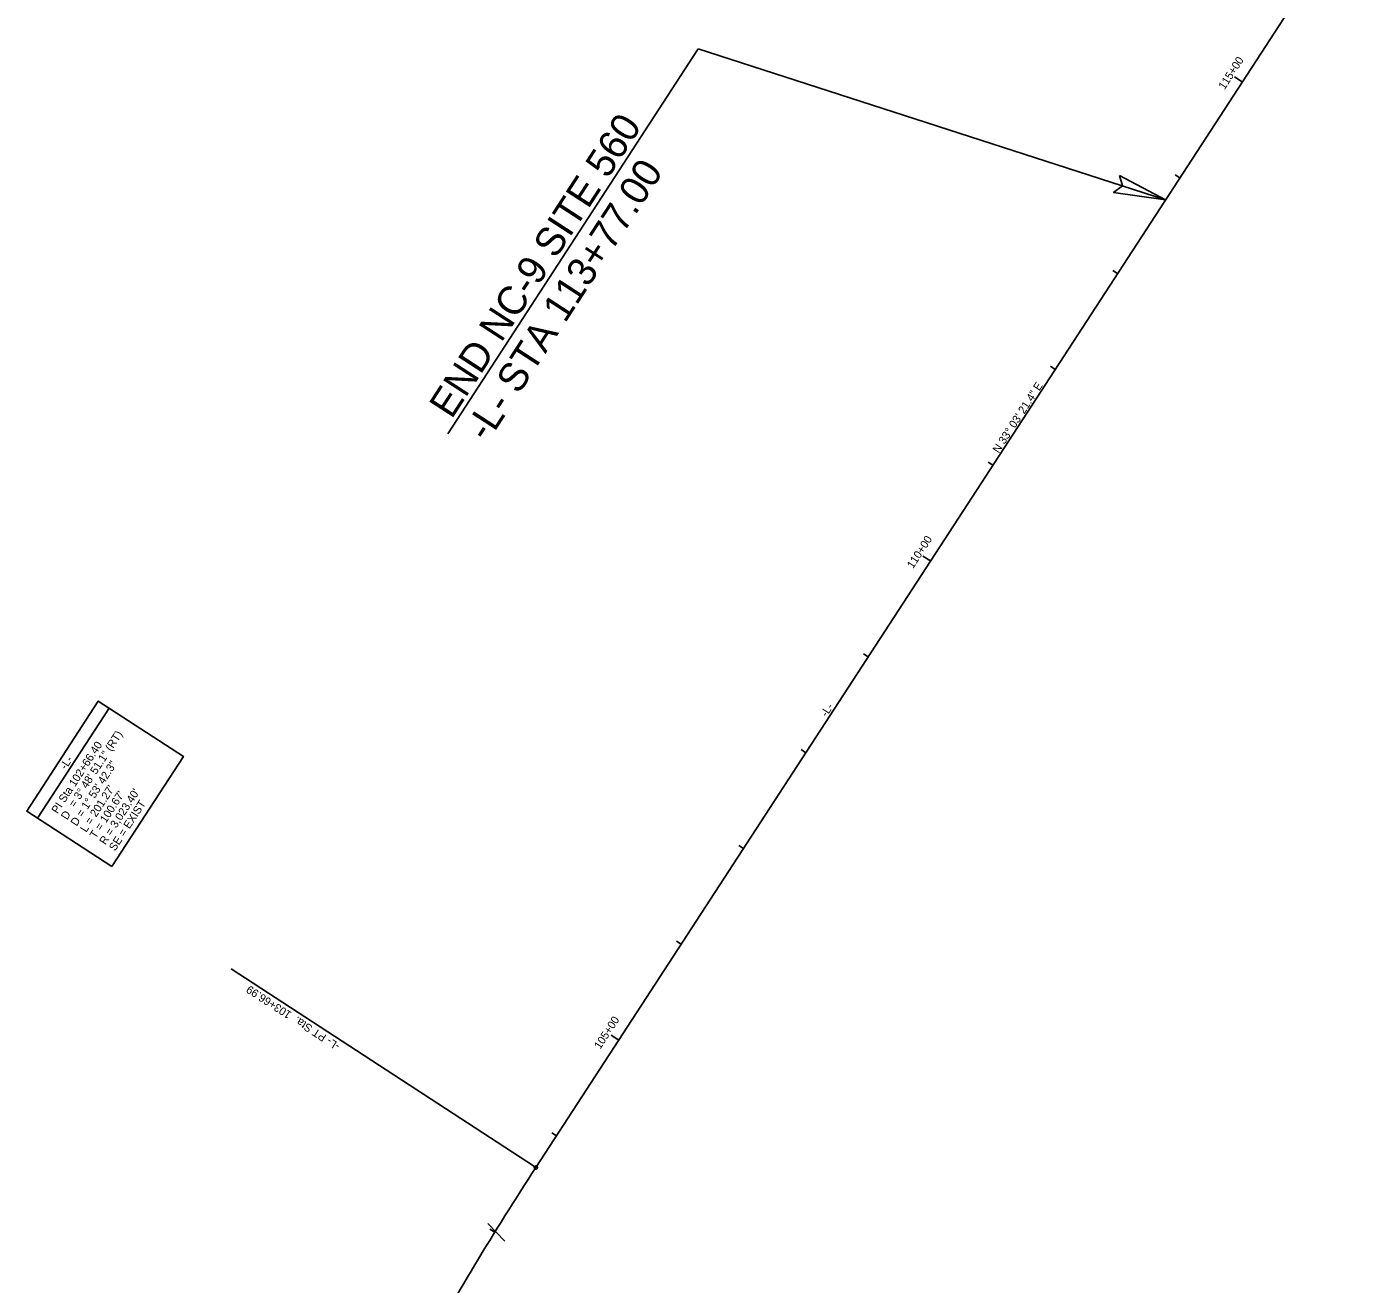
# Model space of a CAD drawing. Extents: x 1019959 to 1023888, y 635993 to 644996.
# Drawn here: x 1022370 to 1023541, y 643068 to 644168 of the extents above; entities that cross this region are included whole.
import ezdxf

# ---------------------------------------------------------------- set-up
doc = ezdxf.new("R2010")
doc.units = 0
for name, color, linetype in [('Cogo Default Point CELL', 7, 'Continuous'), ('COGO Default Point Elevation', 7, 'Continuous'), ('COGO Default Point Number', 7, 'Continuous'), ('Exist Other Culture Well CELL', 7, 'Continuous'), ('Exist Roads EOT', 7, 'Continuous'), ('Exist Structure Minor Pipes CMP 18 Inch Cogo Comment', 7, 'Continuous'), ('Exist Structure Minor Pipes CMP 18 Inch Cogo Number', 7, 'Continuous'), ('Exist Structure Minor Pipes CMP 24 Inch Cogo Number', 7, 'Continuous'), ('Exist Utilities Power Pole CELL', 7, 'Continuous'), ('Exist Utilities Power Pole Cogo Elevation', 7, 'Continuous'), ('Exist Utilities Power Pole Cogo Number', 7, 'Continuous')]:
    doc.layers.add(name, color=color, linetype=linetype)

msp = doc.modelspace()

# ---------------------------------------------------------------- linework, layer by layer
at = {"layer": 'COGO Default Point Elevation'}
for p, q in [((1023379.3, 644035.7), (1023375.1, 644038.4)), ((1023324.7, 643951.9), (1023320.5, 643954.6)), ((1023270.2, 643868.1), (1023266, 643870.8)), ((1023215.6, 643784.3), (1023211.4, 643787)), ((1023106.5, 643616.6), (1023102.3, 643619.4)), ((1023052, 643532.8), (1023047.8, 643535.6)), ((1022997.4, 643449), (1022993.2, 643451.7)), ((1022942.9, 643365.2), (1022938.7, 643367.9)), ((1022833.8, 643197.6), (1022829.6, 643200.3)), ((1022779.9, 643113.4), (1022775.6, 643116))]:
    msp.add_line(p, q, dxfattribs=at)
at = {"layer": 'COGO Default Point Number'}
for p, q in [((1023433.8, 644119.5), (1023427.1, 644123.9)), ((1023161.1, 643700.5), (1023154.4, 643704.8)), ((1022888.3, 643281.4), (1022881.6, 643285.8))]:
    msp.add_line(p, q, dxfattribs=at)
at = {"layer": 'Exist Other Culture Well CELL'}
for p in [(1022738.8, 643811.7), (1023366.7, 644016.4)]:
    msp.add_line(p, (1022957.7, 644148.5), dxfattribs=at)
at = {"layer": 'Exist Roads EOT'}
msp.add_line((1022814.5, 643170.7), (1022549, 643343.6), dxfattribs=at)
msp.add_circle((1022815.8, 643169.9), 1.5, dxfattribs=at)
at = {"layer": 'Exist Structure Minor Pipes CMP 18 Inch Cogo Comment'}
msp.add_lwpolyline([(1023326.3, 644037.6), (1023366.7, 644016.4), (1023321.2, 644022.7), (1023329.1, 644028.6)], close=True, dxfattribs=at)
at = {"layer": 'Exist Structure Minor Pipes CMP 18 Inch Cogo Number'}
msp.add_line((1022815.8, 643169.9), (1023540.5, 644283.5), dxfattribs=at)
msp.add_arc((1025349.8, 641520.8), 3023.4, 146.9441, 150.7582, dxfattribs=at)
at = {"layer": 'Exist Structure Minor Pipes CMP 24 Inch Cogo Number'}
msp.add_line((1022773.7, 643120.9), (1022788.7, 643105.6), dxfattribs=at)
at = {"layer": 'Exist Utilities Power Pole CELL'}
msp.add_line((1022815.8, 643169.9), (1023540.5, 644283.5), dxfattribs=at)
msp.add_arc((1025349.8, 641520.8), 3023.4, 146.9441, 150.7582, dxfattribs=at)
at = {"layer": 'Exist Utilities Power Pole Cogo Elevation'}
msp.add_line((1022379.8, 643475.4), (1022442.4, 643571.7), dxfattribs=at)
msp.add_lwpolyline([(1022444.8, 643433.2), (1022507.4, 643529.5), (1022432.9, 643577.9), (1022370.3, 643481.6)], close=True, dxfattribs=at)

# ---------------------------------------------------------------- texts
at = {"layer": 'Cogo Default Point CELL'}
for s, p in [('115+00', (1023418.3, 644112.3)), ('110+00', (1023145.7, 643693.3)), ('105+00', (1022872, 643272.9))]:
    msp.add_text(s, height=7, rotation=56.9441, dxfattribs=at).set_placement(p)
at = {"layer": 'Exist Other Culture Well CELL'}
for s, p in [('END NC-9 SITE 560', (1022742, 643823.9)), ('-L- STA 113+77.00', (1022773.4, 643803.5))]:
    msp.add_text(s, height=25, rotation=56.9918, dxfattribs=at).set_placement(p)
at = {"layer": 'Exist Roads EOT'}
msp.add_text('-L- PT Sta.  103+66.99', height=7, rotation=146.9441, dxfattribs=at).set_placement((1022644.9, 643277.8))
at = {"layer": 'Exist Utilities Power Pole Cogo Elevation'}
for s, p in [('= 3%%d 48\' 51.1" (RT)', (1022412.3, 643484.4)), ('PI Sta 102+66.40', (1022397.2, 643478.9)), ('-L-', (1022404.6, 643517.5)), ('D = 1%%d 53\' 42.3"', (1022413.9, 643468)), ("L = 201.27'", (1022422.3, 643462.6)), ("R = 3,023.40'", (1022439.1, 643451.7)), ("T = 100.67'", (1022430.7, 643457.1)), ('SE = EXIST', (1022447.5, 643446.2)), ('D', (1022405.5, 643473.5))]:
    msp.add_text(s, height=7, rotation=56.9906, dxfattribs=at).set_placement(p)
at = {"layer": 'Exist Utilities Power Pole Cogo Number'}
for s, p in [('N 33%%d 03\' 21.4" E', (1023220.7, 643794.3)), ('-L-', (1023070.1, 643563.6))]:
    msp.add_text(s, height=7, rotation=56.9441, dxfattribs=at).set_placement(p)

doc.saveas('drawing.dxf')
